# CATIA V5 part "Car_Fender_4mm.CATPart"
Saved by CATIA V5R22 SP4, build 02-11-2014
Part number: Car_Fender
Material "ｱﾙﾐﾆｳﾑ": density 2710 kg/m3, Young's modulus 7e+10 Pa, Poisson ratio 0.346, thermal expansion 2.36e-05 1/K
Bounding box of the stored display mesh (mm): x -800 to 0, y -40 to 122.298, z 0 to 580
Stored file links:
  \\172.16.16.24\714_東北電子専門学校\2014年度\02_実施プロセス\catia_model_data\CAE_data\Car_modify\Car_Fender_4mm.CATPart
  C:\Program Files\Dassault Systemes\B22\win_b64\startup\materials\red_env_512x512.jpg
  C:\Program Files\Dassault Systemes\B22\win_b64\startup\materials\yellow_env_512x512.jpg

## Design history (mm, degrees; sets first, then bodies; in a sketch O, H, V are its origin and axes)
Set1
  Plane1: type Offset, RefPlane yz-plane, Offset 400, reversed
  Plane2 "平面.2": type Offset, RefPlane Plane1, Offset 400, reversed
Body1 (main body)
  Body2
    Sketch1 on yz-plane, origin (0, 0, 0), H (0, 1, 0), V (0, 0, 1)
      point P1 (40.1932, 0)
      point P2 (100, 50)
      line L1 (100, 50) -> (100, 0)
      point P3 (100, 0)
      line L2 (100, 0) -> (0, 0)
      line L3 (0, 0) -> (0, 450)
      line L4 (0, 450) -> (10, 450)
      point P5 (10, 450)
      spline S1 through (10, 450) (100, 50)
      point P6 (10, 450)
      point P7 (100, 50)
      length L3 = 450
      length L2 = 100
      length L1 = 50
      length L4 = 10
      coincidence: P3 H, P6 P5, P7 P2
      vertical: L1 V, L3 V
      horizontal: L2 H, L4 H
    Sketch2 on Plane1, origin (-400, 0, 0), H (0, 1, 0), V (0, 0, 1)
      point P1 (40.1932, 0)
      point P2 (100, 50)
      line L1 (100, 50) -> (100, 0)
      point P3 (100, 0)
      line L2 (100, 0) -> (0, 0)
      line L3 (0, 0) -> (0, 530)
      line L4 (0, 530) -> (10, 530)
      point P5 (10, 530)
      spline S1 through (10, 530) (100, 50)
      point P6 (10, 530)
      point P7 (100, 50)
      length L3 = 530
      length L2 = 100
      length L1 = 50
      length L4 = 10
      coincidence: P3 H, P6 P5, P7 P2
      vertical: L1 V, L3 V
      horizontal: L2 H, L4 H
    Sketch3 on Plane2, origin (-800, 0, 0), H (0, 1, 0), V (0, 0, 1)
      point P1 (40.1932, 0)
      point P2 (100, 50)
      line L1 (100, 50) -> (100, 0)
      point P3 (100, 0)
      line L2 (100, 0) -> (0, 0)
      line L3 (0, 0) -> (0, 580)
      line L4 (0, 580) -> (10, 580)
      point P5 (10, 580)
      spline S1 through (10, 580) (100, 50)
      point P6 (10, 580)
      point P7 (100, 50)
      length L3 = 580
      length L2 = 100
      length L1 = 50
      length L4 = 10
      coincidence: P3 H, P6 P5, P7 P2
      vertical: L1 V, L3 V
      horizontal: L2 H, L4 H
    Loft1: solid, Sections (Sketch1; Sketch2; Sketch3)
    Body3
      Sketch4 on zx-plane, origin (0, 0, 0), H (-1, 0, 0), V (0, 0, 1)
        line L1 (-46.4952, 240) -> (159.0779, 240)
        arc A1 centre (390, 110) radius 265 from (159.0779, 240) to (655, 109.9999) cw
        point P2 (390, 110)
        line L2 (655, 109.9999) -> (655, -30)
        line L3 (-37.8358, 626.6258) -> (859.9489, 626.6258)
        line L4 (859.9489, 626.6258) -> (850, -30)
        line L5 (850, -30) -> (655, -30)
        line L6 (-37.8358, 626.6258) -> (-46.4952, 240)
        radius A1 = 265
        distance P2 H = 110
        distance V P2 = 390
        distance H L1 = 240
        horizontal: L1 H, L3 H, L5 H
        tangency: L2 A1
        vertical: L2 V
      Pad1: profile Sketch4, direction (0, 1, 0), length 340, mirrored extent
    Intersect1: tool Body3
    Sketch5 on Plane2, origin (-800, 0, 0), H (0, 1, 0), V (0, 0, 1)
      line L1 (0, 580) -> (0, 545)
      line L2 (-5, 540) -> (-40, 540)
      point P2 (-40, 540)
      reference projected line E1 (10, 580) -> (0, 580) from edge [face of Loft1 | face of Loft1]
      reference intersected line E2 (0, 0) -> (0, 580) from face of Loft1
      arc A1 centre (-5, 545) radius 5 from (-5, 540) to (0, 545) ccw
      line L3 (-5, 537) -> (-40, 537)
      arc A2 centre (-5, 545) radius 8 from (-5, 537) to (3, 545) ccw
      line L4 (3, 580) -> (3, 545)
      line L5 (-40, 537) -> (-40, 540)
      line L6 (3, 580) -> (0, 580)
      reference projected line E3 (10, 580) -> (0, 580) from edge [face of Loft1 | face of Loft1]
      distance E1 L2 = 40
      radius A1 = 5
      distance L1 P2 = 40
      length L5 = 3
      length L6 = 3
      radius A2 = 8
      vertical: L1 V, L4 V, L5 V
      horizontal: L2 H, L6 H, L3 H
      coincidence: L1 E2, L6 E3
      tangency: A1 L2, A1 L1, L4 A2, A2 L3
    Shell1: ExtOffset 0, Face (face of Loft1; face of Loft1; face of Pad1 from Sketch4.A1; face of Loft1; face of Pad1 from Sketch4.L1; face of Loft1), IntOffset 4
    Rib1: profile Sketch5, centre curve edge [face of Loft1 | face of Loft1]
    Sketch6 on Plane2, origin (-800, 0, 0), H (0, 1, 0), V (0, 0, 1)
      projected line E1 (96, 0) -> (96, 50) from edge [face of Shell1 | face of Rib1]
      projected curve E2 from edge [face of Shell1 | face of Rib1]
      projected line E3 (10, 575.9815) -> (3, 575.9815) from edge [face of Shell1 | face of Rib1]
      point P6 (3, 575.9815)
      projected line E4 (3, 575.9815) -> (3, 545) from edge [face of Rib1 | face of Rib1]
      projected line E5 (3, 575.9815) -> (3, 391.0887) from edge [face of Rib1 | face of Rib1]
      point P7 (3, 575.9815)
      line L1 (96, 0) -> (36, 0)
      line L2 (36, 0) -> (17.9077, 147.35)
      arc A1 centre (2003, 391.0887) radius 2000 from (17.9077, 147.35) to (3, 391.0887) cw
      angle L1 L2 = 97
      length L1 = 60
      radius A1 = 2000
      horizontal: L1 H
      coincidence: P6 P7
      tangency: A1 L2, A1 E4
    Pad2: profile Sketch6, direction (1, 0, 0), length 10, opposite side length -7
    Sketch7 on yz-plane, origin (0, 0, 0), H (0, 1, 0), V (0, 0, 1)
      projected curve E1 from edge [face of Loft1 | face of Shell1]
      projected curve E2 from edge [face of Loft1 | face of Shell1]
      line L1 (102.8701, 240) -> (91.1158, 240)
      line L2 (88.1158, 237) -> (88.1158, 160)
      line L3 (88.1158, 160) -> (85.1158, 160)
      line L4 (85.1158, 160) -> (85.1158, 237)
      line L5 (91.1158, 243) -> (99.9266, 243)
      offset curve E3 from edge [face of Loft1 | face of Shell1]
      offset curve E4 from edge [face of Loft1 | face of Shell1]
      line L6 (100.111, 260.1164) -> (103.1111, 260.1164)
      reference projected line E5 (0, 240) -> (106.8716, 240) from edge [face of Pad1 from Sketch4.L1 | face of Loft1]
      arc A1 centre (91.1158, 237) radius 3 from (88.1158, 237) to (91.1158, 240) cw
      arc A2 centre (91.1158, 237) radius 6 from (85.1158, 237) to (91.1158, 243) cw
      length L3 = 3
      length L6 = 3
      distance L5 L1 = 3
      distance E5 L3 = 80
      distance L2 E1 = 15
      radius A1 = 3
      radius A2 = 6
      horizontal: L1 H, L3 H, L5 H, L6 H
      vertical: L2 V, L4 V
      tangency: A1 L2, A1 L1, A2 L4, A2 L5
    Rib2: profile Sketch7, centre curve edge [face of Pad1 from Sketch4.L1 | face of Shell1]
    Body4
      Sketch8 on zx-plane, origin (0, 0, 0), H (-1, 0, 0), V (0, 0, 1)
        point P1 (0, 300)
        line L1 (0, 300) -> (127.0171, 520)
        line L2 (127.0171, 520) -> (-100, 520)
        line L3 (-100, 520) -> (-100, 300)
        line L4 (-100, 300) -> (0, 300)
        angle L1 L4 = 120
        distance L4 H = 300
        coincidence: P1 V
        horizontal: L2 H, L4 H
        vertical: L3 V
      Pad3: profile Sketch8, direction (0, 1, 0), length 218, mirrored extent
    Remove1: tool Body4
    Sketch9 on xy-plane, origin (0, 0, 0), H (1, 0, 0), V (0, 1, 0)
      line L1 (-730, -50) -> (-730, -25)
      arc A1 centre (-725, -25) radius 5 from (-730, -25) to (-720, -25) cw
      point P3 (-725, -25)
      line L2 (-720, -25) -> (-720, -50)
      line L3 (-720, -50) -> (-730, -50)
      reference projected line E1 (-800, -40) -> (-800, -5) from edge [face of Rib1 | face of Rib1]
      reference projected line E2 (-5.7993, -40) -> (-800, -40) from edge [face of Rib1 | face of Rib1]
      distance E1 L1 = 70
      length L3 = 10
      distance P3 E2 = 15
      radius A1 = 5
      vertical: L1 V
      tangency: A1 L1, L2 A1
      horizontal: L3 H
    Pocket1: profile Sketch9, direction (0, 0, 1), length 657
    RectPattern1: of Pocket1, direction 1 instances 3, spacing 270, along X axis
    Sketch10 on {plane type Tangent, Support face of Rib2, RefPoint {point type OnSurface, Support face of Rib2, RefPoint {point stored without definition}, Length 0, Direction (0, 0, -1000)}}, origin (-34.1699, 88.723, 188.2636), H (0.9999, -0.0168, 0), V (0, 0, 1)
      point P1 (-15.8247, 1.7364)
      reference projected line E1 (-124.8133, -28.2636) -> (34.1753, -28.2636) from edge [face of Rib2 | face of Rib2]
      reference projected line E2 (34.1753, -28.2636) -> (34.1753, 48.7364) from edge [face of Rib2 | face of Rib2]
      distance P1 E1 = 30
      distance P1 E2 = 50
    Hole1: placed by Sketch10, at (-49.9925, 88.9829, 190) direction (-0.016, -0.9999, 0), diameter 15, through (limit type 3)
    Fillet1: radius 10, on edge [face of Rib1 | face of Rib1]; edge [face of Rib1 | face of Pad3 from Sketch8.L1]
    Chamfer1: length 70, angle 35, on edge [face of Rib2 | face of Rib2]
    Fillet2: radius 5, on edge [face of Rib2 | face of Rib2]; edge [face of Chamfer1 | face of Rib2]; edge [face of Rib2 | face of Chamfer1]
    Fillet3: radius 10, on edge [face of Pad1 from Sketch4.L2 | face of Pad2]
  Add1: tool Body2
